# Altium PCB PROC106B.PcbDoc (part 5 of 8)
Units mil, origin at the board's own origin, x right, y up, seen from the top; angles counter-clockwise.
Board outline 4498.18 x 1060.53 mil, 8 copper layers (Top Layer, GND1, Sig1, PWR1, PWR2, Sig2, GND2, Bottom Layer), stack 69.602 mil thick; 439 components, 327 nets, 1548 pads, 843 vias.
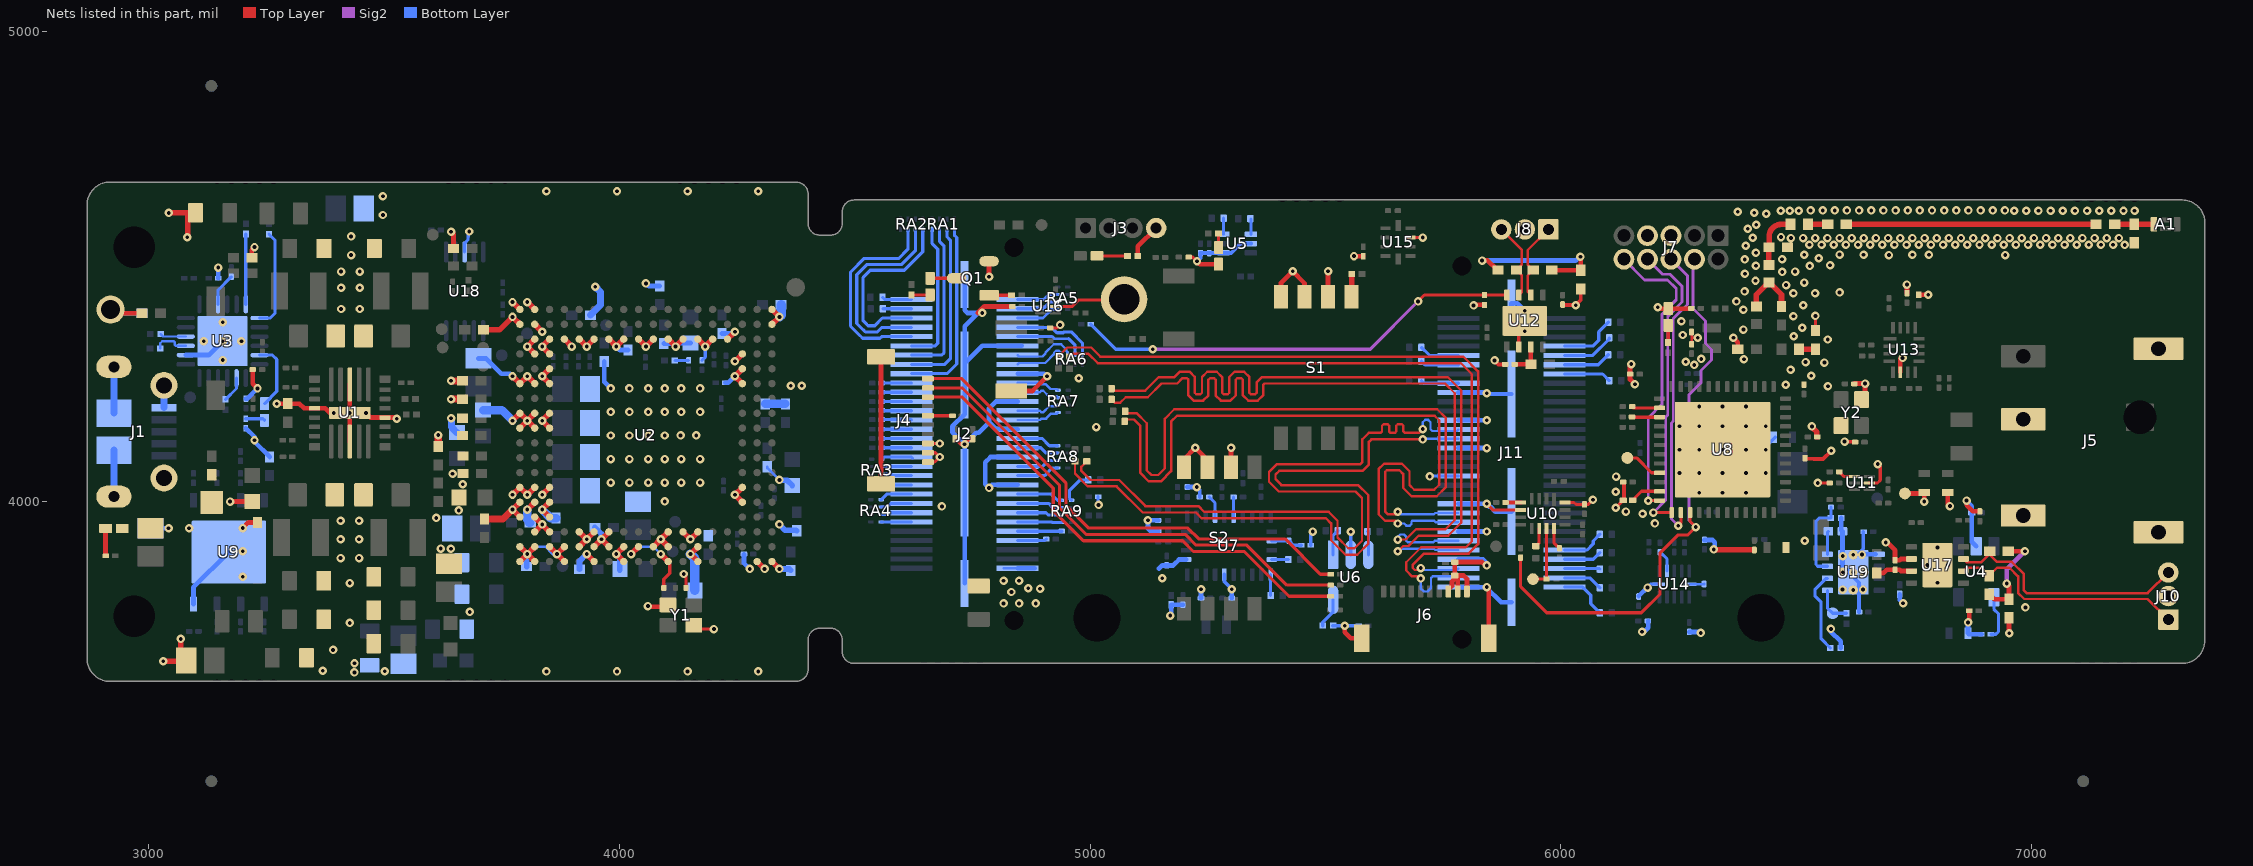
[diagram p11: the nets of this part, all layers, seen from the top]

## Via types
v1: diameter 18, hole 8, Top Layer to Bottom Layer, tented both sides, 804 vias
v2: diameter 19.68, hole 7.87, Top Layer to Bottom Layer, tented both sides, 34 vias
v3: diameter 20, hole 10, Top Layer to Bottom Layer, tented both sides, 3 vias
v4: diameter 18, hole 8, Top Layer to Bottom Layer, 1 vias
v5: diameter 17, hole 7.87, Top Layer to Bottom Layer, 1 vias

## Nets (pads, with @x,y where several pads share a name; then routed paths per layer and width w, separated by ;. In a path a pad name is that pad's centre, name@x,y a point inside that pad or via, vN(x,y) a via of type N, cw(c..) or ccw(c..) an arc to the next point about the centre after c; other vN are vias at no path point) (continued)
GND: C1.1 C2.2 C3.2 C4.2 C5.2 C6.1 C7.2 C8.2 C9.1 C10.1 C11.2 C12.1 C13.1 C14.2 C15.2 C16.2 C17.2 C18.2 C19.2 C20.2 C21.1 C23.2 C24.2 C25.2 C26.2 C27.2 C28.2 C29.2 C30.2 C31.2 C32.2 C33.1 C34.1 C35.2 C36.2 C37.2 C38.2 C39.2 C40.2 C41.2 C42.1 C43.1 C44.1 C45.1 C46.1 C47.1 C48.1 C49.1 C50.2 C51.2 C52.2 C53.2 C54.1 C55.2 C56.2 C57.2 C58.2 C59.2 C60.2 C61.2 C62.2 C63.2 C64.2 C65.2 C66.2 C67.2 C68.2 C69.2 C70.2 C71.2 C72.1 C73.1 C74.2 C75.1 C76.2 C77.1 C78.2 C79.2 C80.2 C81.2 C82.2 C83.2 C84.2 C85.2 C86.2 C87.2 C88.2 C89.2 C90.2 C91.1 C92.1 C94.2 C95.2 C96.2 C97.2 C98.2 C100.1 C101.1 C102.2 C103.2 C104.2 C105.1 C106.1 C107.2 C108.1 C109.1 C110.1 C111.1 C112.2 C113.2 C114.1 C115.2 C116.2 C117.2 C118.2 C119.2 C120.2 C121.2 C122.2 C123.2 C124.1 C125.2 C126.1 C127.2 C128.2 C129.2 C130.1 C131.1 J1.5 J1.6 J1.7 J1.8 J1.9 J1.10 J1.11 J2.20 J2.26 J2.32 J2.38 J2.44 J2.50 J2.MP1 J2.MP2 J2.MP3 J2.MP4 J3.4 J4.8 J4.9 J4.10 J4.11 J4.12 J5.2 J5.3 J5.4 J5.5 J6.8 J6.9 J6.10 J6.11 J6.12 J7.5 J7.7 J8.2 J10.2 J11.18 J11.24 J11.30 J11.36 J11.42 J11.48 J11.54 J11.60 J11.MP1 J11.MP2 J11.MP3 J11.MP4 LD1.2 LD2.2 LD6.2 Q1.2 R3.2 R15.1 R24.1 R29.1 R37.1 R42.2 R52.1 R65.1 R69.1 R73.1 R92.2 R93.2 R96.2 R98.2 R122.2 R125.1 R134.2 R141.2 R158.1 R170.1 R172.1 R180.1 S1.6 S1.7 S1.8 S2.6 S2.7 S2.8 SW2.2 TP12.1 TP15.1 TP20.1 U1.4 U1.11 U1.17 U1.24 U1.27 U2.A1 U2.A2 U2.A6 U2.A8 U2.A11 U2.A13 U2.A15 U2.A17 U2.A18 U2.B6 U2.B8 U2.B9 U2.B10 U2.B11 U2.B12 U2.B13 U2.B14 U2.B15 U2.B16 U2.B17 U2.B18 U2.C6 U2.C7 U2.C8 U2.C12 U2.C13 U2.C14 U2.C16 U2.C17 U2.D16 U2.D17 U2.D18 U2.E3 U2.E16 U2.E17 U2.E18 U2.F3 U2.F16 U2.F17 U2.F18 U2.K16 U2.K17 U2.K18 U2.L16 U2.L17 U2.L18 U2.N3 U2.N16 U2.N17 U2.N18 U2.P3 U2.P16 U2.R3 U2.R16 U2.R17 U2.T4 U2.T5 U2.T6 U2.T7 U2.T8 U2.T9 U2.T10 U2.T11 U2.T12 U2.T13 U2.T14 U2.T15 U2.T16 U2.T17 U2.U1 U2.U17 U2.U18 U2.V1 U2.V17 U2.V18 U3.2 U3.25 U4.2 U5.2 U5.4 U6.2 U7.2 U7.25 U8.49 U9.4 U9.9 U10.6 U10.16 U11.2 U12.2 U12.9@5923.44,4384.46 U13.6 U14.6 U15.3 U16.2 U17.2 U17.9@6799.78,3866 U18.3 U19.5 U19.9@6621.18,3850.46 Y1.2 Y1.4 Y2.2 Y2.4 | length 11299.2
  Top Layer w5.5: C20.2@6277.6,4334.83 6277.6,4349 ; C19.2@6277.6,4361.03 6277.6,4349 ; v1(6290.81,4348.8) 6290.61,4349 6277.6,4349 ; v1@6734.81,4462 v1(6735.03,4461.78) ; v1(6780.09,4440.28) v1@6780.81,4441
  Top Layer w6: C120.2@4915.19,4369.7 4929.78,4369.7 v1(4936.18,4376.1)
  Top Layer w6.7: Y1.4@4159.47,3735.43 4164.9,3730.01 v1(4200.76,3730.01) ; J4.10@4655.33,4084.75 4669.67,4084.75 v1(4680.38,4095.46) 4671.41,4104.44 J4.9@4655.33,4104.44 ; J4.8@4655.33,4124.12 v1(4680.38,4124.12) v1@4680.56,4124.12 ; C16.2@4713.47,4134.05 4725.12,4122.4 v1(4733.36,4122.4) 4744.91,4133.95 C15.2@4750.21,4133.95 ; U16.2@4926.29,4415.28 4962.3,4415.28 4975.97,4428.95 5056.97,4428.95 5056.97,4415.28 TP20.1@5072.16,4430.47 ; R125.1@5209.37,4520.03 5217.97,4520.03 v1(5227,4511) ; U15.3@5680.77,4561.63 v1(5706.58,4561.63) ; v1(5842.34,3996.23) 5842.34,3996.09 5855.35,3983.07 U10.6@5914.31,3983.07 ; U10.16@6008.8,3998.82 6027.93,3998.82 6032.01,3994.74 C117.2@6050.15,3994.74 6058,3994.74 v1(6068,4004.74) ; v1(6116.61,3987.62) C24.2@6132.46,4003.46 ; C21.1@6540.73,4363.78 v1(6540.73,4395.08) ; v1(6545.65,4040.29) C40.2@6571.09,4040.29 ; U11.2@6655.07,4040.29 6672.35,4040.29 6678.29,4046.23 6678.29,4075.35 v1(6673.18,4080.46)
  Top Layer w7: C71.2@4094.48,3817.45 4094.48,3836.09 4106.9,3848.51 4106.9,3867.87 4103.72,3871.04 U2.A8@4103.72,3873.41 ; v1(4136.75,3846.9) 4141.48,3842.17 C14.2@4141.48,3817.27
  Top Layer w8: v1(5299.37,4114.97) v1@5299.37,4116.68 ; v1(5859.11,4300.45) 5867.5,4292.07 C43.1@5881.77,4292.07 ; U12.2@5910.64,4329.34 5910.64,4371.67 U12.9@5923.44,4384.46 ; C105.1@6003.64,4419.31 6004.47,4418.48 6030.47,4418.48 v1(6031.3,4417.65) 6031.3,4417.89 6042.24,4428.83 6042.24,4452.55 C106.1@6042.33,4452.64 ; C26.2@6132.17,4042.21 6132.69,4042.21 6133.86,4041.04 6133.86,4004.87 C24.2@6132.46,4003.46 ; C27.2@6518.42,4093.15 6520.04,4091.53 6536.79,4091.53 6537.06,4091.26 6556.98,4091.26 v1(6574.19,4108.48) ; v1@6602.73,4128.38 v1(6602.58,4128.23) 6603.17,4127.63 6624.26,4127.63 C18.2@6624.86,4127.04
  Top Layer w10: TP12.1@2919.28,4408.64 2927.25,4400.66 C3.2@2986.2,4400.66 ; v1(3173.04,4000.84) C100.1@3220.18,4000.84 ; v1(3200,3944.52) 3211.85,3956.37 C34.1@3231.35,3956.37 ; C32.2@3219.18,4518.49 3219.18,4535.59 v1(3225,4541.42) ; R52.1@3221.07,4281.06 3221.07,4251.35 v1(3231.35,4241.06) ; v1(3272.33,4208.69) C30.2@3295.87,4208.69 3320.4,4208.69 3330.24,4198.85 U1.17@3352.68,4198.85 3375,4198.85 3384.84,4189 v2(3393.23,4189) v2(3427.48,4189) ; U1.24@3427.48,4128.37 v2(3427.48,4189) ; U1.11@3427.48,4249.63 v2(3427.48,4189) ; v1@3526.45,4176.66 3523.96,4179.16 U1.4@3502.28,4179.16 3471.57,4179.16 v2(3461.73,4189) v2(3427.48,4189) ; v1(3642.62,4573.74) 3647.82,4568.54 C31.2@3647.82,4538.34 ; v1@4060.76,3777.29 Y1.2@4095.71,3777.29 ; J4.12@4555.92,4038.49 J4.11@4555.92,4308.18 ; 4761,4401.5 4774.78,4415.28 C72.1@4834.99,4415.28 ; v1(4785.33,4478.19) Q1.2@4785.33,4511.11 ; SW2.2@4832.84,4235.84 4877.59,4235.84 v1(4908.49,4266.74) ; R42.2@5101.31,4522.72 5101.31,4542.78 J3.4@5140.29,4581.75 ; S2.8@5199.37,4073.46 5199.37,4091.17 v1(5223.17,4114.97) 5249.37,4088.77 S2.7@5249.37,4073.46 ; v1(5227,4511) 5232.99,4505.01 LD2.2@5272.84,4505.01 ; S2.6@5299.37,4073.46 v1(5299.37,4114.97) ; S1.8@5405.37,4435.46 5405.37,4465 v1(5430.18,4489.81) 5455.37,4464.63 S1.7@5455.37,4435.46 ; S1.6@5505.37,4435.46 v1(5505.37,4489.81) ; v1(5540.97,3737.11) 5540.97,3723.65 5553.97,3710.65 J6.11@5577.06,3710.65 ; v1(5560.49,4522.26) 5560.83,4521.92 C123.2@5580.17,4521.92 ; J6.8@5761.12,3807.06 5761.12,3813.95 5768.6,3821.44 5768.6,3830.62 5772.77,3834.78 5772.77,3842.77 5773.74,3843.74 C116.2@5774.59,3843.74 ; J6.9@5780.8,3807.06 C116.2@5780.8,3839.39 ; J6.10@5800.49,3810.06 5800.49,3837.09 5793.83,3843.74 5775.3,3843.74 5774.59,3844.45 C115.2@5774.59,3872.2 5833.16,3872.2 5840.17,3865.19 v1(5842.34,3865.19) ; v1(5814.53,4417.41) 5815.67,4418.54 R122.2@5837.64,4418.54 ; v1(5842.34,3819.07) 5846.75,3814.66 J6.12@5846.75,3710.65 ; v1@6146.94,4292 6146.94,4260.11 v1(6157.15,4249.9) ; v1@6206.35,4410.55 LD6.2@6227.85,4410.55 C37.2@6277.18,4410.55 ; v1(6366.4,4348.67) 6375.72,4339.35 C23.2@6375.72,4324.42 ; C17.2@6623.34,4250.88 6623.85,4251.39 6646.11,4251.39 6646.11,4217.48 Y2.4@6646.03,4217.41 ; v1(6689.81,3914) 6693.4,3914 6709.78,3897.62 C108.1@6709.78,3876.02 6719.78,3876 6722.58,3878.8 U17.2@6744.66,3878.8 ; U13.6@6721.06,4275.51 v1@6721.06,4299.75 ; TP15.1@6730.81,4018 6769.81,4018 C122.2@6771.81,4020 v1(6771.81,4000.83) ; C107.2@6735.03,4443.23 v1(6735.03,4461.78) ; R141.2@6760.03,4440.28 v1(6780.09,4440.28) ; C42.1@6821.81,4020 6821.81,3995.69 v1(6826.37,3991.13) ; v1(6861.81,4003) 6861.81,3993.07 6874.85,3980.03 R134.2@6889.73,3980.03 ; v1(6864.78,3744.15) 6867.4,3746.77 C109.1@6867.4,3768.9 ; C110.1@6951.81,3753.93 6951.81,3721.5 v1(6952.41,3720.9) ; v1@6986.5,3776.31 v1(6986.81,3776) ; v1@6721.06,4299.75 6721.06,4304.25 6720.81,4304 6720.81,4300 v1@6721.06,4299.75
  Top Layer w12: v1(3031.17,3661.73) 3068.28,3661.73 v1(3068.28,3709.04) ; v1(3043,4614) 3082.85,4614 3082.85,4566.15 3083,4566 3083,4563 v1(3082,4562) ; C126.1@3721.06,4365.53 3745.45,4365.53 v1(3773.02,4393.1) U2.U18@3788.76,4377.35 ; v1(3773.02,4015.14) U2.F18@3788.76,4030.89 v1(3804.51,4015.14) U2.F17@3820.26,4030.89 ; v1(3773.02,4172.62) U2.L18@3788.76,4188.37 v1(3804.51,4172.62) ; v1(3773.02,4267.11) U2.N18@3788.76,4251.36 v1(3804.51,4267.11) U2.N17@3820.26,4251.36 ; v1(3773.02,4424.59) U2.V18@3788.76,4408.84 ; U2.A18@3788.76,3873.41 v1(3804.51,3889.16) ; U2.B18@3788.76,3904.91 v1(3804.51,3889.16) ; U2.D18@3788.76,3967.9 v1(3773.02,3983.65) U2.E18@3788.76,3999.4 ; U2.K18@3788.76,4156.88 v1(3804.51,4172.62) ; v1(3804.51,3983.65) U2.E17@3820.26,3999.4 ; v1(3804.51,4424.59) U2.V17@3820.26,4408.84 ; U2.A17@3820.26,3873.41 v1(3804.51,3889.16) ; U2.B17@3820.26,3904.91 v1(3804.51,3889.16) ; U2.C17@3820.26,3936.4 v1(3836.01,3952.15) ; U2.D17@3820.26,3967.9 v1(3836.01,3952.15) ; U2.K17@3820.26,4156.88 v1(3804.51,4172.62) ; U2.L17@3820.26,4188.37 v1(3804.51,4172.62) ; U2.R17@3820.26,4314.36 v1(3804.51,4330.1) U2.T17@3820.26,4345.85 ; U2.U17@3820.26,4377.35 v1(3836.01,4361.6) ; v1(3836.01,4015.14) U2.F16@3851.76,4030.89 ; U2.B16@3851.76,3904.91 v1(3867.5,3889.16) ; U2.C16@3851.76,3936.4 v1(3836.01,3952.15) ; U2.D16@3851.76,3967.9 v1(3836.01,3983.65) U2.E16@3851.76,3999.4 ; U2.K16@3851.76,4156.88 v1(3836.01,4172.62) U2.L16@3851.76,4188.37 ; U2.N16@3851.76,4251.36 v1(3836.01,4267.11) U2.P16@3851.76,4282.86 ; U2.R16@3851.76,4314.36 v1(3836.01,4330.1) U2.T16@3851.76,4345.85 ; U2.A15@3883.25,3873.41 v1(3867.5,3889.16) ; U2.B15@3883.25,3904.91 v1(3867.5,3889.16) ; U2.T15@3883.25,4345.85 v1(3899,4330.1) ; U2.B14@3914.75,3904.91 v1(3930.5,3920.65) ; U2.C14@3914.75,3936.4 v1(3930.5,3920.65) ; U2.T14@3914.75,4345.85 v1(3930.5,4330.1) U2.T13@3946.24,4345.85 ; v1(3930.5,3889.16) U2.A13@3946.24,3873.41 ; U2.B13@3946.24,3904.91 v1(3961.99,3920.65) ; U2.C13@3946.24,3936.4 v1(3930.5,3920.65) ; U2.B12@3977.74,3904.91 v1(3961.99,3920.65) ; U2.C12@3977.74,3936.4 v1(3961.99,3920.65) ; U2.T12@3977.74,4345.85 v1(3993.49,4330.1) U2.T11@4009.24,4345.85 ; U2.A11@4009.24,3873.41 v1(3993.49,3889.16) U2.B11@4009.24,3904.91 ; v1(4024.98,3889.16) U2.B10@4040.73,3904.91 ; U2.T10@4040.73,4345.85 v1(4056.48,4330.1) U2.T9@4072.23,4345.85 ; U2.B9@4072.23,3904.91 v1(4087.98,3920.65) ; v1(4087.98,3889.16) U2.A8@4103.72,3873.41 ; U2.B8@4103.72,3904.91 v1(4087.98,3920.65) ; U2.C8@4103.72,3936.4 v1(4087.98,3920.65) ; U2.T8@4103.72,4345.85 v1(4119.47,4330.1) U2.T7@4135.22,4345.85 ; U2.C7@4135.22,3936.4 v1(4150.97,3920.65) U2.C6@4166.72,3936.4 ; U2.A6@4166.72,3873.41 v1(4150.97,3889.16) U2.B6@4166.72,3904.91 ; U2.T6@4166.72,4345.85 v1(4182.46,4330.1) U2.T5@4198.21,4345.85 ; U2.T4@4229.71,4345.85 v1@4243.33,4359.47 ; v1(4245.46,4298.61) U2.R3@4261.2,4314.36 ; U2.E3@4261.2,3999.4 v1(4245.46,4015.14) U2.F3@4261.2,4030.89 ; U2.N3@4261.2,4251.36 v1(4245.46,4267.11) U2.P3@4261.2,4282.86 ; U2.A2@4292.7,3873.41 v1(4308.45,3857.66) ; U2.A1@4324.2,3873.41 v1(4339.94,3857.66) ; U2.U1@4324.2,4377.35 v1(4339.94,4393.1) U2.V1@4324.2,4408.84 ; J4.12@4543.2,4038.49 J4.12@4555.92,4038.49 ; v1(6324.59,3899.2) 6325.24,3898.55 6410.19,3898.55 C86.2@6410.84,3897.89 ; v1(6533.31,4160.3) 6533.31,4158.68 6543.7,4148.29 6543.7,4139.05 6544.53,4138.22 C35.2@6544.67,4138.22
  Top Layer w15: v1(3615.23,4141.98) 3615.31,4141.9 3615.31,4118.19 C33.1@3615.39,4118.11 ; v1(3642.62,4218.19) C58.2@3666.49,4218.19 ; v1(3642.62,4257.19) C57.2@3666.49,4257.19 ; C68.2@3713.57,3963.48 3752.84,3963.48 v1(3773.02,3983.65)
  Bottom Layer w5: v1(3804.51,3889.16) 3820.26,3904.91 3842.53,3904.91 3858.28,3889.16 v1(3867.5,3889.16) ; v1(4024.98,3889.16) 4040.73,3904.91 4072.23,3904.91 v1(4087.98,3889.16)
  Bottom Layer w5.5: C87.2@4314.32,4072.27 C87.2@4314.32,4074.75 ; v1@5840.84,4232.45 v1@5842.34,4230.95
  Bottom Layer w6: C87.2@4314.32,4072.27 v1(4339.95,4046.64) ; v1(6184.15,3818.17) 6184.15,3819.17 6190.34,3825.36 U14.6@6209.55,3825.36
  Bottom Layer w6.7: U18.3@3671.35,4530.99 3671.35,4549.56 3678.49,4556.7 3678.49,4562.64 3679.19,4563.34 3679.19,4572.25 v1(3681.35,4574.41) ; R158.1@4175.56,4300.76 4182.46,4307.66 v1(4182.46,4330.1) ; R37.1@5017.05,4011.07 5017.05,3994.49 v1(5017.88,3993.66) ; v1(5721.24,4054.26) 5722.26,4055.29 J11.36@5782.32,4055.29
  Bottom Layer w8: v1(5226.66,4031.52) 5232.92,4025.26 C13.1@5232.92,4010.48 ; v1(5227,4511) 5234.38,4518.38 C6.1@5234.38,4528.69 C125.2@5252.95,4528.69 5282.89,4528.69 U5.4@5283.23,4529.03 5299.56,4529.03 5319.24,4548.71 U5.2@5341.5,4548.71 ; U7.25@5285.04,3845.7 5285.04,3830.71 v1(5301.01,3814.73) ; R73.1@5468.87,3908 5468.87,3932.94 v1(5472.93,3937) ; R69.1@5516.13,3737.11 v1(5540.97,3737.11) C12.1@5570.91,3737.11 ; U6.2@5553.54,3887.87 v1@5553.54,3935.9 ; v1(5842.34,4230.94) 5843.78,4229.5 J11.MP2@5895.12,4229.5 ; v2(6434.91,4111.11) 6434.91,4117.1 C29.2@6455.28,4137.46 ; U19.9@6611.18,3850.46 6633.26,3828.38 C128.2@6633.26,3766.12 ; U19.9@6630.43,3888.85 6642.17,3900.59 C127.2@6642.17,3936.75
  Bottom Layer w10: TP12.1@2919.28,4408.64 2927.25,4400.66 C2.2@2986.2,4400.66 ; C4.2@3004.01,3943.79 3042.5,3943.79 v1(3042.55,3943.85) ; U3.2@3078.98,4311.9 3127.78,4311.9 v1(3157.31,4341.42) ; U9.4@3095.35,3783.06 3095.35,3818.29 U9.9@3170.35,3893.29 ; R65.1@3147.81,4475.15 v1(3147.81,4497.8) ; R15.1@3206.52,4156.7 3225,4138.23 v1(3225,4131.09) 3225,4127.61 C101.1@3257.08,4095.53 ; R172.1@3206.71,4219.46 3209.74,4219.46 v1(3231.35,4241.06) ; C59.2@3700.56,4304.79 3716.67,4304.79 3749.01,4272.45 3767.67,4272.45 v1(3773.02,4267.11) ; v1@3803.07,3887.72 v1(3804.51,3889.16) ; C130.1@3967.83,4298.36 3967.83,4254.78 v1(3981.48,4241.13) ; v1(3993.49,4330.1) 4001.06,4322.53 C61.2@4018.33,4322.53 ; v1@4018.33,4244.28 v1(4021.48,4241.13) ; v1(4056.48,4464.26) 4062.15,4458.59 C88.2@4085.98,4458.59 ; C96.2@4094.31,4336.45 4113.12,4336.45 v1(4119.47,4330.1) 4126.88,4337.51 C103.2@4150.97,4337.51 ; C91.1@4218.02,4357.96 4241.82,4357.96 v1(4245.46,4361.6) ; R170.1@4224.75,4253.13 4231.48,4253.13 v1(4245.46,4267.11) ; R3.2@4264.78,3889.16 4264.78,3869.84 v1(4276.95,3857.66) ; J2.MP1@4733.36,3826.98 J2.MP2@4733.36,4019.5 v1(4733.36,4122.4) ; J2.MP4@4733.36,4462.02 4733.36,4407.3 4739.16,4401.5 4761,4401.5 ; J2.MP3@4736.75,4297.57 4770.69,4331.51 J2.50@4846.16,4331.51 J2.50@4854.52,4331.51 ; 4761,4400.78 4733.36,4373.14 J2.MP3@4733.36,4269.5 4733.36,4186.13 4707.57,4160.34 4707.57,4148.19 v1(4733.36,4122.4) ; J2.20@4846.16,4036.23 4791.73,4036.23 v1(4785.33,4029.82) 4777.36,4037.79 4777.36,4084.26 4788.39,4095.29 J2.26@4846.16,4095.29 ; J2.32@4846.16,4154.34 4800.11,4154.34 4785.32,4169.13 ; J2.38@4846.16,4213.4 4800.11,4213.4 4785.32,4198.61 4785.32,4169.13 ; J2.44@4846.16,4272.45 4902.77,4272.45 v1(4908.49,4266.74) ; v1(5122.82,3961) 5122.82,3943.75 5128.58,3938 R96.2@5144.96,3938 ; v1(5122.82,3961) R98.2@5144.48,3961 ; 5146.22,3858.44 5152.95,3865.16 C10.1@5162.69,3865.16 5176.2,3865.16 5179.53,3868.48 5179.62,3868.48 5188.83,3877.69 U7.2@5203.84,3877.69 ; v1@5172.1,3758.57 C11.2@5172.1,3781.54 C9.1@5197.1,3781.54 ; R93.2@5206.3,4031.52 v1(5226.66,4031.52) ; C38.2@5235.57,3795.56 v1(5235.57,3814.73) ; C39.2@5301.01,3795.56 v1(5301.01,3814.73) ; J11.60@5782.32,3819.07 5840.84,3819.07 5872.92,3786.98 J11.MP4@5895.12,3786.98 ; J11.54@5782.32,3878.12 5834.41,3878.12 v1@5842.34,3870.19 ; J11.48@5782.32,3937.18 v1@5840.84,3937.18 ; J11.42@5782.32,3996.23 5840.84,3996.23 5847.42,3989.65 5850.7,3989.65 5860.85,3979.5 J11.MP3@5895.12,3979.5 ; J11.30@5782.32,4114.34 v1@5840.84,4114.34 ; J11.24@5782.32,4173.4 v1@5840.84,4173.4 ; J11.18@5782.32,4232.45 v1@5840.84,4232.45 ; 5895.12,4363.6 J11.MP1@5895.12,4422.02 5907.53,4422.02 v2(5923.44,4406.12) ; R180.1@6165.19,3800.17 6183.19,3818.17 v1(6184.15,3818.17) ; v1(6172.42,3724.14) 6176.54,3724.14 6185.59,3733.19 C114.1@6185.59,3747.34 ; C118.2@6272.5,3723.85 6295.09,3723.85 v1(6297.21,3721.73) ; C119.2@6304.91,3919.22 6321.92,3919.22 6326.59,3914.55 v1@6326.59,3899.2 ; v1(6573.56,3730.29) 6573.56,3724.71 6594.25,3704.02 R92.2@6594.25,3689.74 ; R29.1@6595.21,3965.94 6595.21,3940.34 R24.1@6598.09,3937.46 6598.09,3863.56 U19.9@6611.18,3850.46 ; U19.9@6630.43,3888.85 U19.5@6668.27,3888.85 ; C129.2@6719.58,3803.87 6719.58,3791.85 v1(6726.69,3784.74) ; v1(6861.81,4003) 6861.81,4001.72 6872.94,3990.59 C5.2@6872.94,3977 6872.94,3915 U4.2@6882.18,3905.76 ; v1(6864.78,3744.15) C7.2@6864.78,3720.79 6866.57,3719.01 C8.2@6893.18,3719.01 ; v1(4733.36,4122.4) 4757.94,4146.98 4763.16,4146.98 4785.32,4169.13
  Bottom Layer w12: C69.2@3803.07,3862.61 v1@3803.07,3887.72 ; C63.2@3915.38,3856.83 3915.38,3874.05 v1(3930.5,3889.16) ; C64.2@3948.01,3945.83 3961.99,3931.85 v1(3961.99,3920.65) ; v1(3993.49,3889.16) 4001.11,3881.54 C90.2@4001.11,3857.43 C90.2@4001.11,3855.43 ; v1(4339.94,3857.66) 4360.97,3857.66 C94.2@4364,3854.63 ; v1(4339.94,3952.15) 4352.19,3939.9 4375.34,3939.9 C95.2@4376.53,3938.72 ; v1@4348.33,4046 4356.28,4046 C102.2@4367.44,4034.84
  Bottom Layer w15: J1.6@2926.36,4011.35 2926.36,4034.99 J1.7@2926.36,4109.78 ; J1.8@2926.36,4188.52 2926.36,4263.31 ; J1.5@3032.66,4200.33 J1.10@3032.66,4247.58 ; v1(3642.64,4177.66) 3643.22,4177.08 3643.22,4159.64 3645.99,4156.87 3645.99,4155.89 3654.24,4147.64 C83.2@3655.22,4147.64 ; C98.2@3938.33,4396.76 3960.19,4418.63 3960.19,4445.69 v1(3948.76,4457.12)
  Bottom Layer w18: C79.2@3710.6,4195.01 3750.63,4195.01 v1(3773.02,4172.62) ; v1(3804.51,3983.65) 3804.51,3961.8 3807.82,3958.49 3807.82,3956.52 3808.66,3955.68 C67.2@3810.63,3955.68 ; v1(3836.01,3983.65) 3854.19,3965.46 C66.2@3865.49,3965.46 ; C60.2@4309.75,4208.14 C92.1@4352.69,4208.14
  Bottom Layer w19.68: v1(4339.94,4393.1) 4343.63,4396.79 C56.2@4343.63,4419.07
  Bottom Layer w20: v1(4150.97,3889.16) 4160.53,3879.6 C89.2@4160.53,3811.96
  other v1: 3437.24,3637.77 3845,3640 3995,3640 4145,3640 4295,3640 3501.78,3640.53 3370.14,3641.55 3437.41,3657.14 3392.01,3685.56 3427.5,3742.94 5170.1,3758.57 3682.29,3766.43 4060.76,3778.81 6598.2,3813.91 6641.68,3813.91 3427.5,3827.52 5153.05,3837.96 3200,3840.9 6621.18,3850.46 3407.79,3880.66 3447.16,3880.66 6598.73,3884.93 6639.57,3888.2 3200,3895.28 3620.78,3900.91 3642.2,3900.58 6517.93,3917.64 3407.79,3920.66 3447.16,3920.66 5553.54,3936.9 5842.34,3937.18 3086,3944 6199.58,3954.37 3407.79,3960.25 3447.16,3960.25 3611.2,3966.06 6173.42,3975.06 6138.22,3979.46 3658.91,3981.83 4685.21,3990.4 4096.48,4001.13 6116.61,4021.48 3667.38,4037.8 3981.48,4041.13 4021.48,4041.13 4061.48,4041.13 4096.48,4041.13 4131.48,4041.13 4171.48,4041.13 6117.16,4053.82 3645.69,4059.82 3981.48,4091.13 4021.48,4091.13 4061.48,4091.13 4096.48,4091.13 4131.48,4091.13 4171.48,4091.13 5842.34,4114.34 3981.48,4141.13 4021.48,4141.13 4061.48,4141.13 4096.48,4141.13 4130,4141.16 4163.52,4141.2 5012.83,4158.94 5842.34,4173.4 3527.25,4176.66 3981.48,4191.13 4021.48,4191.13 4061.48,4191.13 4096.48,4191.13 4131.48,4191.13 4171.48,4191.13 4061.48,4241.13 4096.48,4241.13 4131.48,4241.13 4171.48,4241.13 6567.18,4245.75 4363.84,4246.9 4387.42,4246.76 6477.81,4248.79 6646.18,4251.46 4975.95,4262.89 6531.81,4268 6487.81,4281 6283.37,4291.04 6149.27,4292.84 6559.81,4296 6519.81,4297.07 6265.28,4297.89 3157.31,4301.42 6388.81,4303 6298.05,4303.82 6725.81,4306 3117.31,4341.42 3197.31,4341.42 6566.81,4345 6494.81,4351.83 6258.88,4354.6 6387.81,4366 6512.81,4370 3157.31,4381.42 6256.1,4383.77 6493.81,4394.36 4771,4401.5 6387.81,4408 3408.97,4409.8 3448.34,4409.8 6205.62,4413.56 6514.81,4418 6372.91,4426 6493.81,4443.5 6539.81,4443.5 6591.81,4445 6390.06,4447.19 3408.97,4454.79 3448.34,4454.79 6478.34,4460.66 6516.81,4466 6413.31,4469.81 6390.89,4484.62 3408.97,4489.38 3448.34,4489.38 6470.39,4488.58 6497.5,4489.4 6528.81,4501.37 6414.18,4501.81 6571.81,4502.89 6390.62,4515.12 6469.81,4515.56 6547.81,4517.37 3430,4524.36 6696.81,4524.37 6943.81,4524.37 6517.09,4524.83 6642.81,4524.83 6746.64,4524.83 6781.79,4524.83 6591.83,4525.52 6414.36,4529.3 6392.81,4544.21 6527.94,4546.17 6553.74,4546.16 6579.54,4546.16 6605.34,4546.16 6631.14,4546.16 6656.94,4546.16 6682.74,4546.16 6708.54,4546.16 6734.34,4546.16 6760.15,4546.16 6785.95,4546.16 6811.75,4546.15 6837.55,4546.15 6863.35,4546.15 6889.15,4546.15 6914.95,4546.15 6940.75,4546.15 6966.55,4546.15 6992.35,4546.15 7018.16,4546.15 7043.96,4546.15 7069.76,4546.15 7095.56,4546.14 7121.36,4546.14 7147.16,4546.14 7172.96,4546.14 7197.56,4546.03 6488.63,4560.48 6514.43,4560.48 6540.23,4560.48 6566.03,4560.48 6591.83,4560.48 6617.64,4560.47 6643.44,4560.47 6669.24,4560.47 6695.04,4560.47 6720.84,4560.47 6746.64,4560.47 6772.44,4560.47 6798.24,4560.47 6824.04,4560.47 6849.84,4560.47 6875.65,4560.46 6901.45,4560.46 6927.25,4560.46 6953.05,4560.46 6978.85,4560.46 7004.65,4560.46 7030.45,4560.46 7056.25,4560.46 7082.05,4560.46 7107.85,4560.45 7133.66,4560.45 7159.46,4560.45 7185.26,4560.45 6407.43,4561.08 6467.49,4562.71 3430,4563.95 6396.81,4580.37 6414.7,4588.53 3497.67,4609.47 6436.24,4611.91 6410.81,4614.37 6375.72,4616.37 6962.81,4618.37 6988.61,4618.37 7014.41,4618.37 7040.21,4618.37 7066.02,4618.37 7091.82,4618.38 7117.62,4618.38 7143.42,4618.38 7169.22,4618.38 7195.02,4618.38 7218.63,4618.38 6466.94,4618.59 6486.08,4618.57 6505.22,4618.56 6530.23,4619.19 6556.03,4619.19 6581.83,4619.19 6607.64,4619.19 6633.44,4619.19 6659.24,4619.19 6685.04,4619.19 6710.84,4619.2 6736.64,4619.2 6762.44,4619.2 6788.24,4619.2 6814.04,4619.2 6839.84,4619.2 6865.65,4619.2 6891.45,4619.2 6917.25,4619.2 6943.05,4619.2 3497.67,4649.07 3845,4660 3995,4660 4145,4660 4295,4660
  other v2: 6621.18,3813.06 6799.78,3828.6 6598.54,3850.46 6643.82,3850.46 6778.13,3866 6821.43,3866 6621.18,3887.86 6799.78,3903.4 6293.77,4019.57 6343.38,4019.57 6392.99,4019.57 6251.84,4061.5 6293.77,4061.5 6343.38,4061.5 6392.99,4061.5 6434.91,4061.5 6251.84,4111.11 6293.77,4111.11 6343.38,4111.11 6392.99,4111.11 6251.84,4160.71 6293.77,4160.71 6343.38,4160.71 6392.99,4160.71 6434.91,4160.71 6293.77,4202.64 6343.38,4202.64 6392.99,4202.64 5923.44,4362.81
HD_AR_BSS_LOGGER: J2.43 RA1.5 | length 392.4
  Bottom Layer w6.7: J2.43@4620.57,4272.45 4695.91,4272.45 4716.55,4293.08 4716.55,4561.64 4711.71,4566.48 RA1.5@4711.71,4578.92
HD_AR_CS1: J2.19 RA3.8 | length 66
  Bottom Layer w6.7: RA3.8@4557.6,4043.61 4564.98,4036.23 J2.19@4620.57,4036.23
HD_AR_DMM_CLK: J2.10 R11.2 | length 93.9
  Bottom Layer w6.7: J2.10@4846.16,3937.81 4939.87,3937.81 R11.2@4940,3937.94
HD_AR_DMM_SYNC: J2.8 R10.2 | length 62
  Bottom Layer w6.7: J2.8@4846.16,3918.12 4904.12,3918.12 R10.2@4907,3921
HD_AR_DP0: J2.27 R88.2 | length 63.3
  Bottom Layer w6.7: R88.2@4557.28,4114.97 J2.27@4620.57,4114.97
HD_AR_DP1: J2.29 R130.2 | length 63.3
  Bottom Layer w6.7: R130.2@4557.28,4134.63 J2.29@4620.54,4134.63
HD_AR_DP2: J2.31 R132.2 | length 63.3
  Bottom Layer w6.7: R132.2@4557.28,4154.34 J2.31@4620.57,4154.34
HD_AR_DP3: J2.33 R133.2 | length 63.6
  Bottom Layer w6.7: R133.2@4557.28,4174.75 4619.84,4174.75 J2.33@4620.57,4174.03
HD_AR_DP4: J2.35 R135.2 | length 63.4
  Bottom Layer w6.7: R135.2@4557.6,4194.78 4558.66,4193.71 J2.35@4620.57,4193.71
HD_AR_DP5: J2.37 R137.2 | length 61.7
  Bottom Layer w6.7: R137.2@4558.99,4213.11 4620.27,4213.11 J2.37@4620.57,4213.4
HD_AR_DP6: J2.39 R138.2 | length 60.7
  Bottom Layer w6.7: R138.2@4559.91,4233.08 J2.39@4620.57,4233.08
HD_AR_DP7: J2.41 R140.2 | length 61.7
  Bottom Layer w6.7: R140.2@4559.05,4252.4 4620.2,4252.4 J2.41@4620.57,4252.77
HD_AR_HOSTINTR1: J2.16 RA9.3 | length 96.7
  Bottom Layer w6.7: J2.16@4846.16,3996.86 4911.7,3996.86 4920.93,3987.64 RA9.3@4939.02,3987.64
HD_AR_MCUCLKOUT: J2.47 RA1.7 | length 337.1
  Bottom Layer w6.7: J2.47@4620.57,4311.82 4684.38,4311.82 4689.75,4317.19 4689.75,4543.29 4680.21,4552.83 RA1.7@4680.21,4578.92
HD_AR_OSC_CLKOUT: J2.45 RA1.6 | length 365.4
  Bottom Layer w6.7: J2.45@4620.57,4292.14 4691.37,4292.14 4703.15,4303.91 4703.15,4556.09 4695.96,4563.28 RA1.6@4695.96,4578.92
HD_AR_PMIC_CLKOUT_SOP2: J2.49 RA1.8 | length 305.1
  Bottom Layer w6.7: J2.49@4620.57,4331.51 4671.19,4331.51 4676.35,4336.67 4676.35,4536.83 4664.47,4548.71 RA1.8@4664.47,4578.92
HD_AR_SCL: J2.55 RA2.5 | length 403.1
  Bottom Layer w6.7: J2.55@4620.57,4390.56 4558.74,4390.56 4542.53,4374.36 4528.16,4374.36 4523.26,4379.26 4523.08,4379.26 4517.69,4384.65 4517.69,4476.95 4532.85,4492.11 4605.41,4492.11 4644.48,4531.18 RA2.5@4644.48,4578.92
HD_AR_SDA: J2.53 RA2.6 | length 422.5
  Bottom Layer w6.7: J2.53@4620.57,4370.88 4558.01,4370.88 4548.08,4360.96 4522.61,4360.96 4517.71,4365.86 4517.53,4365.86 4504.29,4379.1 4504.29,4482.5 4526.45,4504.65 4600.21,4504.65 4628.74,4533.18 RA2.6@4628.74,4578.92
HD_AR_TCK: J2.15 RA4.6 | length 67.9
  Bottom Layer w6.7: RA4.6@4555.92,3988.99 4562.46,3988.99 4564.05,3990.58 4570.71,3990.58 4576.99,3996.86 J2.15@4620.57,3996.86
HD_AR_TDI: J2.11 RA4.8 | length 64.6
  Bottom Layer w6.7: RA4.8@4555.92,3957.49 J2.11@4620.57,3957.49
HD_AR_TDO_SOP0: J2.17 RA4.5 | length 69.5
  Bottom Layer w6.7: RA4.5@4555.92,4004.74 4567.74,4016.55 J2.17@4620.57,4016.55
HD_AR_TMS: J2.13 RA4.7 | length 66.3
  Bottom Layer w6.7: RA4.7@4555.92,3973.24 4565.66,3973.24 4569.6,3977.18 J2.13@4620.57,3977.18
HD_AR_WARMRST: J2.51 RA2.7 | length 440.7
  Bottom Layer w6.7: 4520.18,4517.34 4490.89,4488.05 4490.89,4373.55 4511.98,4352.46 4512.16,4352.46 4517.06,4347.56 4553.63,4347.56 4557.27,4351.19 J2.51@4620.57,4351.19 ; 4520.31,4517.2 4593.34,4517.2 4612.99,4536.85 RA2.7@4612.99,4578.92
HD_SPI_CLK1: J2.21 RA3.7 | length 64.4
  Bottom Layer w6.7: RA3.7@4557.6,4059.36 4577.67,4059.36 4581.11,4055.92 J2.21@4620.57,4055.92
HD_SPI_MISO1: J2.25 RA3.5 | length 68.4
  Bottom Layer w5.5: J2.25@4620.57,4095.29 J2.25@4623.14,4092.71
  Bottom Layer w6.7: RA3.5@4557.6,4090.85 4562.03,4095.29 J2.25@4620.57,4095.29
HD_SPI_MOSI1: J2.23 RA3.6 | length 63.2
  Bottom Layer w6.7: RA3.6@4557.6,4075.11 4558.1,4075.6 J2.23@4620.57,4075.6
INTN: R95.1 TP46.1 U10.11 | length 136.3
  Top Layer w6.7: TP46.1@5940.71,3836.09 R95.1@5969.43,3836.09 U10.11@5969.43,3943.7
JTAG_TCK: J7.8 U8.25 | length 641.4
  Top Layer w6.7: v1(6196.43,3977.5) 6196.69,3977.25 U8.25@6235.11,3977.25
  Sig2 w5.95: J7.8@6183.84,4515.56 6215.86,4483.54 6231.63,4483.54 6256.95,4458.22 6256.95,4424.52 6226.86,4394.43 6226.86,4184.49 6222.79,4180.41 6222.79,4003.85 v1(6196.43,3977.5)
JTAG_TDI: J7.4 R113.1 U8.27 | length 1235.2
  Top Layer w6.7: R113.1@5914.31,3881.68 5914.31,3820.01 5969.79,3764.53 6170.98,3764.53 6210.78,3804.32 6210.78,3892.11 6248.13,3929.46 6268.98,3929.46 v1(6286.18,3946.67) 6274.48,3958.37 U8.27@6274.48,3977.25
  Sig2 w5.95: J7.4@6283.84,4515.56 6285.63,4513.77 6280.73,4513.77 6280.73,4411 6307.28,4384.45 6307.28,4336.71 6319.92,4324.08 6319.92,4301.6 6297.53,4279.21 6297.53,4253.04 6272.1,4227.61 6272.1,3960.75 v1(6286.18,3946.67)
JTAG_TDO: J7.6 U8.26 | length 630.9
  Top Layer w6.7: v1(6249.18,3949.46) 6254.8,3955.08 U8.26@6254.8,3977.25
  Sig2 w5.95: J7.6@6233.84,4515.56 6268.84,4480.56 6268.84,4419.59 6238.75,4389.51 6238.75,4171.9 6234.68,4167.82 6234.68,3963.97 v1(6249.18,3949.46)
JTAG_TMS: J7.10 U8.24 | length 636.5
  Top Layer w6.7: v1(6185.59,4002.46) 6185.97,4002.84 U8.24@6209.52,4002.84
  Sig2 w5.95: J7.10@6133.84,4515.56 6177.75,4471.64 6226.7,4471.64 6245.05,4453.29 6245.05,4429.45 6214.97,4399.36 6214.97,4207.63 6185.59,4178.25 v1(6185.59,4002.46)
MRDY: TP16.1 U8.21 | length 81.4
  Top Layer w6.7: TP16.1@6141.18,4093.46 6160.9,4093.46 6192.47,4061.9 U8.21@6209.52,4061.9
NetA1_4: A1.4 C99.1 C104.1 | length 83.6
  Top Layer w12: C99.1@7176.11,4589.83 C104.1@7217.64,4589.83 A1.4@7259.72,4589.83
NetC8_1: C8.1 U4.4 | length 95.6
  Bottom Layer w6.7: C8.1@6913.21,3719.01 6923.97,3719.01 6929.42,3724.46 6929.42,3762.5 6919.58,3772.33 U4.4@6919.58,3797.49
NetC13_2: C13.2 U7.9 | length 46.9
  Bottom Layer w6.7: C13.2@5252.95,4010.48 5265.35,3998.08 U7.9@5265.35,3968.74
NetC21_2: C21.2 L1.2 | length 34.8
  Top Layer w12: L1.2@6505.92,4324.41 C21.2@6540.73,4324.41
NetC22_1: C22.1 L6.2 L9.1 | length 124
  Top Layer w12: L6.2@6415.18,4415.16 6415.18,4440.34 6440.86,4466.02 L9.1@6441.85,4466.02 ; L9.1@6442.83,4466.02 6468.51,4440.34 C22.1@6468.51,4415.16
NetC24_1: C24.1 U8.23 | length 65.2
  Top Layer w6.7: C24.1@6152.19,4003.46 6171.26,4022.52 U8.23@6209.52,4022.52
NetC41_1: C41.1 L9.2 L10.1 | length 120.7
  Top Layer w12: L9.2@6441.85,4503.42 C41.1@6441.85,4540.91 ; C41.1@6442.24,4540.91 6442.24,4563.52 cw(c6468.46,4563.52) 6468.46,4589.73 6487.76,4589.73 L10.1@6487.76,4589.83
NetC43_2: C43.2 FL12.1 U12.3 | length 71.5
  Top Layer w10: C43.2@5901.79,4292.07 5901.96,4292.24 5936.06,4292.24 FL12.1@5936.23,4292.41 U12.3@5936.23,4329.34
NetC93_1: C93.1 C99.2 | length 528.9
  Top Layer w12: C93.1@6606.06,4589.85 C99.2@7135,4589.69
NetC93_2: C93.2 L10.2 | length 41.5
  Top Layer w12: L10.2@6525.16,4589.83 C93.2@6566.69,4589.83
NetC106_2: C106.2 R119.1 R126.2 | length 345.7
  Top Layer w10: v1(5832.42,4512.62) 5832.96,4513.16 5843.92,4513.16 5864.3,4492.77 R119.1@5866.27,4492.77 ; R126.2@5980.6,4492.48 5980.84,4492.25 6042.09,4492.25 C106.2@6042.33,4492.01 6042.33,4519.71 v1(6041.47,4520.56)
  Bottom Layer w10: v1(5832.42,4512.62) 6031.33,4512.62 6039.28,4520.56 v1(6041.47,4520.56)
NetC108_2: C108.2 FL3.1 U17.3 | length 78.4
  Top Layer w10: FL3.1@6667.81,3855.69 FL3.1@6668.13,3856 ; FL3.1@6670.79,3848.88 6684.78,3848.88 6691.9,3856 C108.2@6709.78,3856 6719.78,3856 6722.58,3853.2 U17.3@6744.66,3853.2
NetC110_2: C110.2 R114.1 R117.2 | length 201.6
  Top Layer w10: R117.2@6909.66,3803.83 6920.2,3793.3 C110.2@6951.81,3793.3 6951.81,3822 v1(6947.13,3826.69) ; R114.1@6950.32,3895.33 v1(6985.56,3895.33)
  Sig2 w10: v1(6947.13,3826.69) 6947.13,3856.9 v1(6985.56,3895.33)
NetD1_2: D1.2 FL2.2
NetJ2_2: J2.2 L16.1 | length 65.4
  Bottom Layer w6: J2.2@4816.76,3859.07 J2.2@4846.16,3859.07
  Bottom Layer w10: J2.2@4846.16,3859.07 J2.2@4882.13,3859.07
  other v1: 4816.08,3784.39 4849.03,3784.39 4884.53,3784.39 4832.84,3808.7 4893.73,3815.76 4868.31,3816.51 4816.08,3832.48 4849.03,3832.48
NetJ2_12: J2.12 RA9.1 | length 93.4
  Bottom Layer w6.7: J2.12@4846.16,3957.49 4918.74,3957.49 4920.09,3956.14 RA9.1@4939.02,3956.14
NetJ2_14: J2.14 RA9.2 | length 95.1
  Bottom Layer w6.7: J2.14@4846.16,3977.18 4906.26,3977.18 4911.55,3971.89 RA9.2@4939.02,3971.89
NetJ2_18: J2.18 RA9.4 | length 98.3
  Bottom Layer w6.7: J2.18@4846.16,4016.55 4917.47,4016.55 4930.63,4003.38 RA9.4@4939.02,4003.38
NetJ2_22: J2.22 RA8.1 | length 91.6
  Bottom Layer w6.7: J2.22@4846.16,4055.92 4903.41,4055.92 4919.74,4072.25 RA8.1@4931.04,4072.25
NetJ2_24: J2.24 RA8.2 | length 90
  Bottom Layer w6.7: J2.24@4846.16,4075.6 4899.11,4075.6 4911.5,4088 RA8.2@4931.04,4088
NetJ2_28: J2.28 RA8.3 | length 89.5
  Bottom Layer w6.7: J2.28@4846.16,4114.97 4895.26,4114.97 4906.48,4103.74 RA8.3@4931.04,4103.74
NetJ2_30: J2.30 RA8.4 | length 91.2
  Bottom Layer w6.7: J2.30@4846.16,4134.66 4898.38,4134.66 4913.55,4119.49 RA8.4@4931.04,4119.49
NetJ2_34: J2.34 RA7.1 | length 92.2
  Bottom Layer w5.1: J2.34@4846.16,4174.03 4893.39,4174.03 4896.38,4177.02 4906.49,4177.02 4916.95,4187.48 4929.14,4187.48 RA7.1@4931.69,4190.03
NetJ2_36: J2.36 RA7.2 | length 93
  Bottom Layer w5.1: J2.36@4846.16,4193.71 4893.39,4193.71 4896.38,4190.72 4900.81,4190.72 4913.32,4203.23 4929.14,4203.23 RA7.2@4931.69,4205.78
NetJ2_40: J2.40 RA7.3 | length 92.8
  Bottom Layer w5.1: J2.40@4846.16,4233.08 4893.39,4233.08 4896.38,4236.08 4900.4,4236.08 4912.4,4224.08 4929.14,4224.08 RA7.3@4931.69,4221.53
NetJ2_42: J2.42 RA7.4 | length 92
  Bottom Layer w5.1: J2.42@4846.16,4252.77 4893.39,4252.77 4896.38,4249.78 4906.07,4249.78 4916.02,4239.82 4929.14,4239.82 RA7.4@4931.69,4237.27
NetJ2_46: J2.46 RA6.1 | length 109.4
  Bottom Layer w5.1: J2.46@4846.16,4292.14 4849.15,4295.13 4904.62,4295.13 4923.39,4313.9 4923.39,4316.3 4928.48,4321.4 4932.71,4321.4 4935.69,4318.41 4935.69,4314.63 RA6.1@4936.59,4313.73
NetJ2_48: J2.48 RA6.2 | length 132.9
  Bottom Layer w5.1: J2.48@4846.16,4311.82 4849.15,4308.83 4898.94,4308.83 4905.21,4315.1 4905.21,4317.51 4922.81,4335.1 4938.38,4335.1 4949.39,4324.09 4949.39,4320.93 4951.44,4318.88 4951.44,4314.63 RA6.2@4952.34,4313.73
NetJ2_52: J2.52 RA6.3 | length 149.6
  Bottom Layer w5.1: 4918.66,4351.19 4919.8,4351.19 4924.09,4346.9 4954.3,4346.9
  Bottom Layer w6.7: J2.52@4846.16,4351.19 4918.66,4351.19 4919.23,4350.63 ; 4954.3,4346.9 4968.09,4333.12 RA6.3@4968.09,4313.73
NetJ2_54: J2.54 RA6.4 | length 176.3
  Bottom Layer w6.7: J2.54@4846.16,4370.88 4917.93,4370.88 4929.31,4359.5 4943.06,4359.5 4944.66,4361.1 4959.77,4361.1 4983.83,4337.03 RA6.4@4983.83,4313.73
NetJ2_56: J2.56 RA5.1 | length 92.2
  Bottom Layer w6.7: J2.56@4846.16,4390.56 4899.92,4390.56 4918.45,4409.09 RA5.1@4930.68,4409.09
NetJ2_57: J2.57 R14.1 | length 60.7
  Bottom Layer w6.7: R14.1@4559.91,4410.25 J2.57@4620.57,4410.25
NetJ2_58: J2.58 RA5.2 | length 90.6
  Bottom Layer w6.7: J2.58@4846.16,4410.25 4900.66,4410.25 4915.25,4424.84 RA5.2@4930.68,4424.84
NetJ2_59: J2.59 R12.1 | length 63.5
  Bottom Layer w6.7: R12.1@4558.95,4434.59 4563.61,4429.93 J2.59@4620.57,4429.93
NetJ2_60: J2.60 RA5.3 | length 88.9
  Bottom Layer w6.7: J2.60@4846.16,4429.93 4901.39,4429.93 4912.05,4440.59 RA5.3@4930.68,4440.59
NetJ4_1: J4.1 R185.2 | length 1055.8
  Top Layer w6.7: J4.1@4655.33,4261.92 4727.18,4261.92 4948.54,4040.55 4948.54,3992.57 4996.72,3944.4 5207.59,3944.4 5230.44,3921.55 5414.12,3921.55 5489.18,3846.49 R185.2@5510.98,3846.49
NetJ4_2: J4.2 R184.2 | length 1057.5
  Top Layer w6.7: J4.2@4655.33,4242.23 4727.91,4242.23 4935.14,4035 4935.14,3987.02 4991.16,3931 5202.04,3931 5224.89,3908.15 5332.96,3908.15 5417.83,3823.28 R184.2@5511.15,3823.28
NetJ4_3: J4.3 R183.2 | length 1058.5
  Top Layer w6.7: J4.3@4655.33,4222.55 4728.65,4222.55 4921.74,4029.45 4921.74,3981.47 4985.61,3917.6 5196.49,3917.6 5219.34,3894.75 5327.41,3894.75 5422.54,3799.62 R183.2@5510.6,3799.62
NetJ4_5: J4.5 R182.2 | length 52.4
  Top Layer w6.7: J4.5@4655.33,4183.18 R182.2@4707.7,4183.18
NetJ8_1: J8.1 R126.1 U12.6 | length 169.8
  Top Layer w5.2: U12.6@5936.23,4439.58 5929.61,4446.2 5929.61,4480.86 R126.1@5941.23,4492.48 5929.61,4504.11 5929.61,4535.06 J8.1@5973.44,4578.88
NetJ8_3: J8.3 R119.2 U12.7 | length 169.8
  Top Layer w5.2: J8.3@5873.44,4578.88 5917.26,4535.06 5917.26,4504.39 R119.2@5905.64,4492.77 5917.26,4481.15 5917.26,4446.2 U12.7@5910.64,4439.58
NetJ10_1: J10.1 R117.1 U17.6 | length 518.2
  Top Layer w5.2: U17.6@6854.9,3853.2 6861.52,3859.83 6893.28,3859.83 6909.66,3843.44 R117.1@6909.66,3843.2 6926.69,3860.23 6952.6,3860.23 6971.1,3841.73 6971.1,3806.84 6984.11,3793.82 7246.4,3793.82 J10.1@7290.23,3750
NetJ10_3: J10.3 R114.2 U17.7 | length 519.1
  Top Layer w5.2: U17.7@6854.9,3878.8 6861.52,3872.18 6893.28,3872.18 6909.57,3888.47 6909.57,3889.61 6926.6,3872.58 6957.72,3872.58 6983.45,3846.85 6983.45,3811.96 6989.23,3806.18 7246.4,3806.18 J10.3@7290.23,3850
NetJ11_7: J11.7 R150.1 | length 124.3
  Bottom Layer w6.7: J11.7@6007.91,4330.88 6067.62,4330.88 6080.27,4343.52 6080.27,4361.21 R150.1@6100.82,4381.76
NetJ11_9: J11.9 R151.1 | length 111.6
  Bottom Layer w6.7: J11.9@6007.91,4311.19 6067.76,4311.19 6102.62,4346.05 R151.1@6102.62,4348.48
NetJ11_10: J11.10 R152.2 | length 85.7
  Bottom Layer w6.7: R152.2@5703.72,4328.4 5720.93,4311.19 J11.10@5782.32,4311.19
NetJ11_11: J11.11 R153.1 | length 101.3
  Bottom Layer w6.7: J11.11@6007.91,4291.51 6079.44,4291.51 R153.1@6100.53,4312.59
NetJ11_12: J11.12 R154.2 | length 81.7
  Bottom Layer w6.7: R154.2@5703.72,4298.93 5711.14,4291.51 J11.12@5782.32,4291.51
NetJ11_13: J11.13 R155.1 | length 100.7
  Bottom Layer w6.7: J11.13@6007.91,4271.82 6088.51,4271.82 R155.1@6102.76,4257.57
NetJ11_16: J11.16 R157.2 | length 80.9
  Bottom Layer w6.7: R157.2@5703.72,4257.72 5709.31,4252.14 J11.16@5782.32,4252.14
NetJ11_26: J11.26 R142.2 | length 1605
  Top Layer w5.1: R142.2@4992.71,4085.96 4981.47,4074.71 4981.47,4065.91 5000.74,4046.64 5061.89,4046.64 5117.3,3991.23 5230.19,3991.23 5242.49,3978.93 5506.79,3978.93 5525.53,3960.18 5525.53,3924.37 5548.32,3901.58 5561.57,3901.58 5577.38,3917.4 5577.38,4008.41 5563.64,4022.15 5400.57,4022.15 5379.97,4042.75 5379.97,4063.65 5395.98,4079.66 5573.04,4079.66 5578.42,4085.05 5578.42,4133.29 5591.7,4146.57 5614,4146.57 5617.03,4146.57 5620.05,4149.59 5620.05,4161.86 5623.07,4164.88 5632.13,4164.88 5635.15,4161.86 5635.15,4149.59 5638.17,4146.57 5647.23,4146.57 5650.25,4149.59 5650.25,4161.86 5653.27,4164.88 5662.33,4164.88 5665.35,4161.86 5665.35,4149.59 5668.37,4146.57 5680.45,4146.57 5688,4146.57 5698.28,4146.57 v1(5706.58,4154.87) ; R142.2@4992.84,4085.84 R142.2@4994,4087
  Bottom Layer w5.1: v1(5706.58,4154.87) 5706.58,4169.11 5711.8,4174.33 5717.99,4174.33 5722.99,4169.33 5722.99,4154.5 5726.78,4150.72 5779.33,4150.72 J11.26@5782.32,4153.71
NetJ11_28: J11.28 R143.2 | length 1523.3
  Top Layer w5.1: R143.2@4967.77,4085.96 4967.77,4060.23 4995.06,4032.94 5056.22,4032.94 5111.62,3977.53 5224.51,3977.53 5236.82,3965.23 5501.12,3965.23 5511.83,3954.51 5511.83,3918.7 5542.65,3887.88 5567.24,3887.88 5591.08,3911.73 5591.08,4014.08 5569.32,4035.85 5406.24,4035.85 5393.67,4048.42 5393.67,4057.98 5401.65,4065.96 5578.71,4065.96 5592.12,4079.37 5592.12,4127.61 5597.37,4132.87 v1(5706.58,4132.87)
  Bottom Layer w5.1: v1(5706.58,4132.87) 5707.74,4134.03 J11.28@5782.32,4134.03
NetJ11_44: J11.44 R144.2 | length 1497.2
  Top Layer w5.1: R144.2@5074.38,4192.66 5078.25,4188.79 5098.82,4188.79 5120.42,4167.19 5120.42,4067.08 5130.29,4057.21 5144.56,4057.21 5158.4,4071.06 5158.4,4176.46 5178.82,4196.88 5737.33,4196.88 5755.13,4179.07 5755.13,4030.95 5736.32,4012.13 5682.72,4012.13 5664.75,4030.11 5664.75,4059.58 5656.87,4067.45 5629.99,4067.45 5626.58,4064.04 5626.58,3979.62 5632.65,3973.55 v1@5648.39,3973.55 ; v1@5648.2,3973.74 v1(5653.67,3979.2)
  Bottom Layer w5.1: v1(5653.67,3979.2) 5659.32,3973.55 5730.04,3973.55 5733.03,3976.55 J11.44@5782.32,3976.55
NetJ11_46: J11.46 R145.2 | length 1504.8
  Top Layer w5.1: R145.2@5073.28,4171.22 5077.14,4175.09 5093.14,4175.09 5106.72,4161.52 5106.72,4061.4 5124.61,4043.51 5150.23,4043.51 5172.1,4065.38 5172.1,4170.79 5184.5,4183.18 5731.65,4183.18 5741.43,4173.4 5741.43,4036.62 5730.64,4025.83 5688.4,4025.83 5678.45,4035.78 5678.45,4065.25 5662.55,4081.15 5624.32,4081.15 5612.88,4069.72 5612.88,3973.95 5626.98,3959.85 5647.7,3959.85 v1@5653.67,3953.89
  Bottom Layer w5.1: v1(5653.67,3954.2) 5667.21,3954.2 5671.64,3949.77 5679.08,3949.77 5682.59,3953.28 5682.59,3957.95 5684.49,3959.85 5730.75,3959.85 5733.75,3956.86 J11.46@5782.32,3956.86
NetJ11_50: J11.50 R146.2 | length 1543.1
  Top Layer w5.1: R146.2@5045.59,4217.79 5052.35,4211.04 5064.14,4211.04 5075.54,4222.44 5122.54,4222.44 5151.56,4251.46 5184.94,4251.46 5196.54,4263.06 5205.36,4263.06 5208.6,4259.82 5208.6,4226.36 5219.86,4215.1 5240.04,4215.1 5251.3,4226.36 5251.3,4259.6 5254.54,4262.84 5263.36,4262.84 5266.6,4259.6 5266.6,4226.36 5277.86,4215.1 5298.04,4215.1 5309.3,4226.36 5309.3,4259.6 5312.54,4262.84 5321.36,4262.84 5324.6,4259.6 5324.6,4226.36 5335.86,4215.1 5356.04,4215.1 5367.3,4226.36 5367.3,4248.23 5370.54,4251.46 5754.07,4251.46 5774.59,4230.94 5774.59,3961.67 5754.79,3941.87 5692.17,3941.87 5670.45,3920.15 v1(5653.67,3920.15)
  Bottom Layer w5.1: v1(5653.67,3920.15) 5653.67,3925.88 5658.7,3930.92 5666.92,3930.92 5671.19,3926.64 5671.19,3918.07 5674.77,3914.5 5729.2,3914.5 5732.19,3917.49 J11.50@5782.32,3917.49
NetJ11_51: J11.51 R186.1 | length 92.4
  Bottom Layer w6.7: J11.51@6007.91,3897.81 6055.63,3897.81 6068.62,3910.8 6068.62,3917.09 R186.1@6082.75,3931.22
NetJ11_52: J11.52 R147.2 | length 1570.3
  Top Layer w5.1: R147.2@5045.59,4240.79 5050.24,4236.14 5116.87,4236.14 5145.89,4265.16 5179.27,4265.16 5190.86,4276.76 5211.04,4276.76 5222.3,4265.5 5222.3,4232.04 5225.54,4228.8 5234.36,4228.8 5237.6,4232.04 5237.6,4265.27 5248.86,4276.54 5269.04,4276.54 5280.3,4265.27 5280.3,4232.04 5283.54,4228.8 5292.36,4228.8 5295.6,4232.04 5295.6,4265.27 5306.86,4276.54 5327.04,4276.54 5338.3,4265.27 5338.3,4232.04 5341.54,4228.8 5350.36,4228.8 5353.6,4232.04 5353.6,4253.9 5364.86,4265.16 5759.75,4265.16 5788.29,4236.62 5788.29,3956 5760.46,3928.17 5697.84,3928.17 5690.57,3920.9 5676.12,3906.45 5664.97,3906.45 v1(5653.67,3895.15)
  Bottom Layer w5.1: v1(5653.67,3895.15) 5659.32,3900.8 5729.95,3900.8 5732.94,3897.81 J11.52@5782.32,3897.81
NetJ11_53: J11.53 R187.1 | length 80.7
  Bottom Layer w6.7: J11.53@6007.91,3878.12 6068.61,3878.12 R187.1@6082.75,3892.26
NetJ11_55: J11.55 R188.1 | length 75.3
  Bottom Layer w6.7: J11.55@6007.91,3858.44 6081.73,3858.44 R188.1@6082.75,3857.41
NetJ11_56: J11.56 R148.2 | length 1558.8
  Top Layer w5.1: R148.2@4932.76,4309.41 4940.74,4317.39 4940.74,4317.51 4946.33,4323.1 4946.45,4323.1 4951.41,4328.06 5002.21,4328.06 5021.81,4308.46 5792.97,4308.46 5824.19,4277.23 5824.19,3910.48 5803.86,3890.15 5708.91,3890.15 5685.03,3866.26 5685.03,3860.1 5689.68,3855.44 5697.91,3855.44 v1(5702.06,3859.59)
  Bottom Layer w5.1: v1(5702.06,3859.59) 5706.21,3855.44 J11.56@5779.33,3855.44 ; J11.56@5779.33,3855.44 J11.56@5782.32,3858.44 J11.56@5779.33,3855.44
NetJ11_57: J11.57 R189.1 | length 83.6
  Bottom Layer w6.7: J11.57@6007.91,3838.75 6061.56,3838.75 R189.1@6082.75,3817.56
NetJ11_58: J11.58 R149.2 | length 1577.7
  Top Layer w5.1: R149.2@4956.17,4308.66 4961.86,4314.36 4996.54,4314.36 5016.13,4294.76 5787.29,4294.76 5810.49,4271.56 5810.49,3916.15 5798.19,3903.85 5703.24,3903.85 5671.33,3871.93 5671.33,3854.43 5684.01,3841.74 5697.91,3841.74 v1(5702.06,3837.59)
  Bottom Layer w5.1: v1(5702.06,3837.59) 5702.06,3836.59 5702.06,3816.44 5708.83,3809.68 5716.42,3809.68 5724.03,3817.29 5724.03,3838.14 5727.64,3841.74 J11.58@5779.33,3841.74 ; J11.58@5779.33,3841.74 J11.58@5782.32,3838.75 J11.58@5779.33,3841.74
NetJ11_59: J11.59 R190.1 | length 107.9
  Bottom Layer w6.7: J11.59@6007.91,3819.07 6046.09,3819.07 6063.24,3801.92 6063.24,3784.04 R190.1@6082.75,3764.53
NetLD1_1: LD1.1 R39.2 | length 58.5
  Top Layer w10: LD1.1@2908.64,3943.79 2908.64,3886.21 R39.2@2909.26,3885.59
NetLD2_1: LD2.1 R13.2 | length 30.2
  Top Layer w6.7: LD2.1@5272.84,4540.44 R13.2@5272.84,4570.64
NetLD3_2: LD3.2 R42.1 | length 64.5
  Top Layer w6.7: LD3.2@5014.74,4522.72 R42.1@5079.26,4522.72
NetLD4_1: LD4.1 U3.17 | length 145.2
  Bottom Layer w6.7: U3.17@3235.64,4311.9 3263.27,4311.9 3272.33,4302.84 3272.33,4234.73 LD4.1@3246.44,4208.84
NetLD4_2: LD4.2 R15.2 | length 41.3
  Bottom Layer w6.7: R15.2@3206.52,4176.73 3243.12,4176.73 LD4.2@3246.44,4173.41
NetLD5_1: LD5.1 R107.2 | length 39.5
  Top Layer w6.7: R107.2@4620.57,4439.65 LD5.1@4660.11,4439.65
NetLD5_2: LD5.2 Q1.3 | length 56.2
  Top Layer w6.7: LD5.2@4660.11,4475.09 Q1.3@4716.29,4475.09
NetLD6_1: LD6.1 R17.2 | length 36.5
  Top Layer w6.7: R17.2@6227.85,4338.67 LD6.1@6227.85,4375.12
NetQ1_1: Q1.1 R108.2 | length 47.6
  Top Layer w6.7: Q1.1@4785.33,4439.06 R108.2@4832.96,4439.06
NetR2_1: R2.1 R174.1 | length 29.3
  Bottom Layer w6.7: R2.1@4117.94,4300.76 R174.1@4147.23,4300.76
NetR16_2: R16.2 S1.5 | length 49
  Top Layer w12: S1.5@5555.37,4435.46 R16.2@5555.37,4484.46
NetR20_2: R20.2 R29.2 U19.3 | length 175.3
  Bottom Layer w6.7: U19.3@6566.06,3863.26 6545.65,3863.26 6541.75,3867.15 6541.75,3959.03 6548.66,3965.94 R29.2@6573.16,3965.94 6573.66,3966.44 R20.2@6573.66,3988.94
NetR24_2: R24.2 U19.4 | length 50.4
  Bottom Layer w5.5: U19.4@6566.06,3888.6 U19.4@6566.91,3888.6
  Bottom Layer w6.7: U19.4@6566.06,3888.85 6566.06,3935.25 R24.2@6568.28,3937.46
NetR27_2: R27.2 TP10.1 U19.1 | length 82.5
  Bottom Layer w6.7: U19.1@6566.06,3812.08 6566.06,3774.58 TP10.1@6577.18,3763.46 6577.29,3763.57 R27.2@6606.39,3763.57
NetR30_2: R30.2 U10.10 | length 40.3
  Top Layer w6.7: R30.2@5946.67,3906.31 5953.68,3913.33 U10.10@5953.68,3943.7
NetR40_2: R40.2 U3.9 | length 70.1
  Bottom Layer w6.7: U3.9@3147.47,4419.75 3147.47,4449.8 R40.2@3175.78,4478.12
NetR41_1: R41.1 U3.3 | length 73.8
  Bottom Layer w5: R41.1@3024.94,4326.25 3024.94,4337.12 3029.08,4341.27 3053.43,4341.27 3055.31,4339.38 3055.31,4333.93 3057.67,4331.58 U3.3@3078.98,4331.58
NetR51_2: R51.2 U5.1 | length 32.4
  Bottom Layer w5.5: U5.1@5341.5,4568.4 U5.1@5341.64,4568.54
  Bottom Layer w6.7: U5.1@5341.5,4568.4 R51.2@5341.5,4600.58
NetR57_2: R57.2 U5.6 | length 34.4
  Bottom Layer w5.5: U5.6@5283.23,4568.4 U5.6@5283.59,4568.76
  Bottom Layer w6.7: U5.6@5283.59,4568.76 R57.2@5283.59,4602.69
NetR58_2: R58.2 RA9.5 | length 72.3
  Bottom Layer w6.7: RA9.5@4960.68,4003.38 4956,4008.06 4956,4024 4978.94,4046.94 R58.2@4996.2,4046.94
NetR60_1: R60.1 U3.4 | length 55.6
  Bottom Layer w5: R60.1@3025.57,4356.6 3030.91,4351.27 U3.4@3078.98,4351.27
NetR61_2: R61.2 U3.20 | length 55
  Bottom Layer w6.7: R61.2@3163.55,4217.78 3186.84,4241.06 U3.20@3186.84,4263.09
NetR62_2: R62.2 U3.12 | length 149.4
  Bottom Layer w6.7: U3.12@3206.52,4419.75 R62.2@3206.51,4569.19
NetR63_2: R63.2 U3.13 | length 210.4
  Bottom Layer w6.7: U3.13@3235.64,4390.64 3258.76,4390.64 3268.29,4400.17 3268.29,4556.37 R63.2@3255.87,4568.78
NetR66_2: R66.2 R122.1 U12.8 | length 953.3
  Top Layer w6.7: v1(5696.52,4426) 5710.07,4439.58 R122.1@5837.64,4439.58 U12.8@5885.05,4439.58
  Sig2 w6.7: v1(5132.78,4324.44) 5594.96,4324.44 v1(5696.52,4426)
  Bottom Layer w6.7: R66.2@5001.44,4377.56 5054.55,4324.44 v1(5132.78,4324.44)
NetR67_2: R67.2 U6.1 | length 55.2
  Bottom Layer w6.7: U6.1@5516.13,3887.87 5516.13,3928.91 R67.2@5526.13,3938.91
NetR68_2: R68.2 U6.3 | length 53.7
  Bottom Layer w5.5: R68.2@5590.94,3935.21 R68.2@5590.94,3938.91
  Bottom Layer w6.7: R68.2@5589.08,3937.06 5590.94,3935.21 U6.3@5590.94,3887.87
NetR69_2: R69.2 U6.5 | length 64.2
  Bottom Layer w6.7: R69.2@5494.09,3737.11 5494.09,3744.51 5516.13,3766.56 U6.5@5516.13,3792.16
NetR70_1: R70.1 U7.19 | length 35.3
  Bottom Layer w6.7: U7.19@5385.92,3877.69 R70.1@5421.2,3877.69
NetR71_1: R71.1 U7.20 | length 44.4
  Bottom Layer w6.7: R71.1@5383.46,3801.26 U7.20@5383.46,3845.7
NetR72_2: R72.2 R73.2 U7.17 | length 66.8
  Bottom Layer w6.7: U7.17@5385.92,3917.06 5422.6,3917.06 R72.2@5422.76,3917.23 5431.98,3908 R73.2@5448.84,3908
NetR74_2: R74.2 U11.4 | length 36.5
  Top Layer w6.7: R74.2@6591.11,4063.92 6600.96,4054.07 U11.4@6623.57,4054.07
NetR76_1: R76.1 U14.8 | length 46.5
  Bottom Layer w6.7: R76.1@6210.78,3893.43 6225.29,3878.92 U14.8@6225.29,3852.92
NetR79_1: R79.1 U14.12 | length 29.7
  Bottom Layer w5.5: U14.12@6274.51,3825.36 6303.81,3825.36 R79.1@6304.11,3825.66
NetR86_2: R86.2 U8.15 | length 58.7
  Top Layer w6.7: R86.2@6151.04,4180.57 6151.61,4180.01 U8.15@6209.52,4180.01
NetR87_2: R87.2 U8.14 | length 60.1
  Top Layer w6.7: R87.2@6151.19,4202.46 6154.4,4199.26 6195.18,4199.26 6195.18,4199.69 U8.14@6209.52,4199.69
NetR92_1: R92.1 U19.2 | length 173.6
  Bottom Layer w6.7: U19.2@6566.06,3837.67 6563.27,3837.67 6540.08,3814.48 6540.08,3799.65 6552.66,3787.07 6552.66,3709.28 R92.1@6572.2,3689.74
NetR97_1: R97.1 U7.11 | length 41.7
  Bottom Layer w6.7: U7.11@5304.72,3968.74 R97.1@5304.72,4010.48
NetR99_1: R99.1 U10.12 | length 46.8
  Top Layer w6.7: U10.12@5985.18,3943.7 5985.18,3913.36 R99.1@5996.83,3901.71
NetR100_2: R100.2 U10.5 | length 31.9
  Top Layer w8: R100.2@5882.43,3998.82 U10.5@5914.31,3998.82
